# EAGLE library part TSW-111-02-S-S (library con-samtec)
THROUGH-HOLE .025" SQ POST HEADER Source: Samtec TSW.pdf
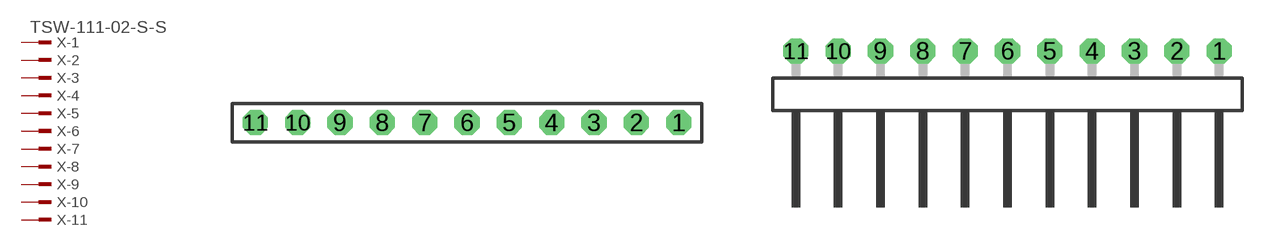
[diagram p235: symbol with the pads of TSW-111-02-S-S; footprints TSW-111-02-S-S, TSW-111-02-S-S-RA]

Designator prefix X; gates -1=MPINV -2=MPIN -3=MPIN -4=MPIN -5=MPIN -6=MPIN -7=MPIN -8=MPIN -9=MPIN -10=MPIN -11=MPIN

## TSW-111-02-S-S (OC_FARNELL: unknown; OC_NEWARK: unknown)  [TSW-111-02-S-S]
1  -1:1  pas
2  -2:1  pas
3  -3:1  pas
4  -4:1  pas
5  -5:1  pas
6  -6:1  pas
7  -7:1  pas
8  -8:1  pas
9  -9:1  pas
10  -10:1  pas
11  -11:1  pas

## TSW-111-02-S-S-RA (OC_FARNELL: unknown; OC_NEWARK: unknown)  [TSW-111-02-S-S-RA]
Pads as for TSW-111-02-S-S

## Footprint TSW-111-02-S-S (pad centres in mm)
THROUGH-HOLE .025" SQ POST HEADER Source: Samtec TSW.pdf
drill 1 pad 1.5 octagon: 1 12.7,0; 2 10.16,0; 3 7.62,0; 4 5.08,0; 5 2.54,0; 6 0,0; 7 -2.54,0; 8 -5.08,0; 9 -7.62,0; 10 -10.16,0; 11 -12.7,0

## Footprint TSW-111-02-S-S-RA (pad centres in mm)
THROUGH-HOLE .025" SQ POST HEADER Source: Samtec TSW.pdf
drill 1 pad 1.5 octagon: 1 12.7,1.524; 2 10.16,1.524; 3 7.62,1.524; 4 5.08,1.524; 5 2.54,1.524; 6 0,1.524; 7 -2.54,1.524; 8 -5.08,1.524; 9 -7.62,1.524; 10 -10.16,1.524; 11 -12.7,1.524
